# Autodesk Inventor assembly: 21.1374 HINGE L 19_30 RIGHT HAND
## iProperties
Created: 2007-01
Part Number: 21.1374 HINGE L 19_30 RIGHT HAND
Document SubType Name: Assembly
Designer: Andy Moles
Author: Andy Moles
